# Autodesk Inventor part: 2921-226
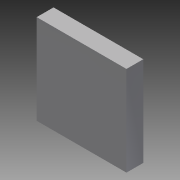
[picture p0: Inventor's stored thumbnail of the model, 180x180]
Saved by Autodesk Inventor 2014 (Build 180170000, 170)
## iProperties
Company: NHTSA/VRTC
Created: 2012-08
Part Number: 2921-226
Material: Steel, Mild
Document SubType Name: Modeling
Designer: Mike Vanvoorhis
Density: 7.86 g/cm^3
Mass: 193.203 g
Surface Area: 70.9676 cm^2
Volume: 24.5806 cm^3
Project: CHILD SIDE IMPACT SLED
Description: IMPACTOR STOP TUBE END PLATE
Stock Number: PL 9.5 (3/8") x 50.8 (2") x 50.8 (2")
Appearance: Steel
Author: Dave Walker
Title: Impactor Stop Tube End Plate
Subject: Child Side Impact Sled
Revision Number: A
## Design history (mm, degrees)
sketch "Sketch1"
  geometry: L1 (0, 0)-(50.8, 0); L2 (50.8, 0)-(50.8, 50.8); L3 (50.8, 50.8)-(0, 50.8); L4 (0, 50.8)-(0, 0)
  constraints: 8 end point, 2 parallel, 1 horizontal, 1 perpendicular
  dimensions: "d0" = 50.8 distance of L3.end L2.end; "d1" = 50.8 distance of L2.end L1.end
extrude "Extrusion1" new body sketch "Sketch1" distance "d2" = 9.525; taper "d3" = 0 deg
body "Solid1"
